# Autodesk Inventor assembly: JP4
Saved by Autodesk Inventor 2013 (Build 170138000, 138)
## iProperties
Created: 2021-02
Part Number: JP4
Document SubType Name: Assembly
Designer: Fede
Author: Fede
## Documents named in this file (2)
- C:\0000 FEDE\16GB\0000 INTERIOR\DE_TMP_BAS\BAS_DTON - demora conexion al energizar\pcb\BOR\turn on\Imported Components\BAS_DTON\JP4.iam
- C:\0000 FEDE\16GB\0000 INTERIOR\DE_TMP_BAS\BAS_DTON - demora conexion al energizar\pcb\BOR\turn on\Imported Components\BAS_DTON\bornera3x1.iam
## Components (1 placed, 1 different names)
1. bornera3x1:1 [sub-assembly]
